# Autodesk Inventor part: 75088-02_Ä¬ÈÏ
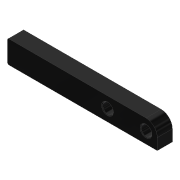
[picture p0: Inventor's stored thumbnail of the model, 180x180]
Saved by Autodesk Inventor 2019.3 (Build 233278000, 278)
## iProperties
Created: 2010-06
Part Number: 75088-02_Ä¬ÈÏ
Material: Ogólny
Document SubType Name: Modeling
Designer: CADENGINEERING4
Density: 1 g/cm^3
Appearance: Gładki — czarny
Author: CADENGINEERING4
Revision Number: ÈÎºÎ
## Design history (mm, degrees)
feature "NONE"
node "Bryła1"
